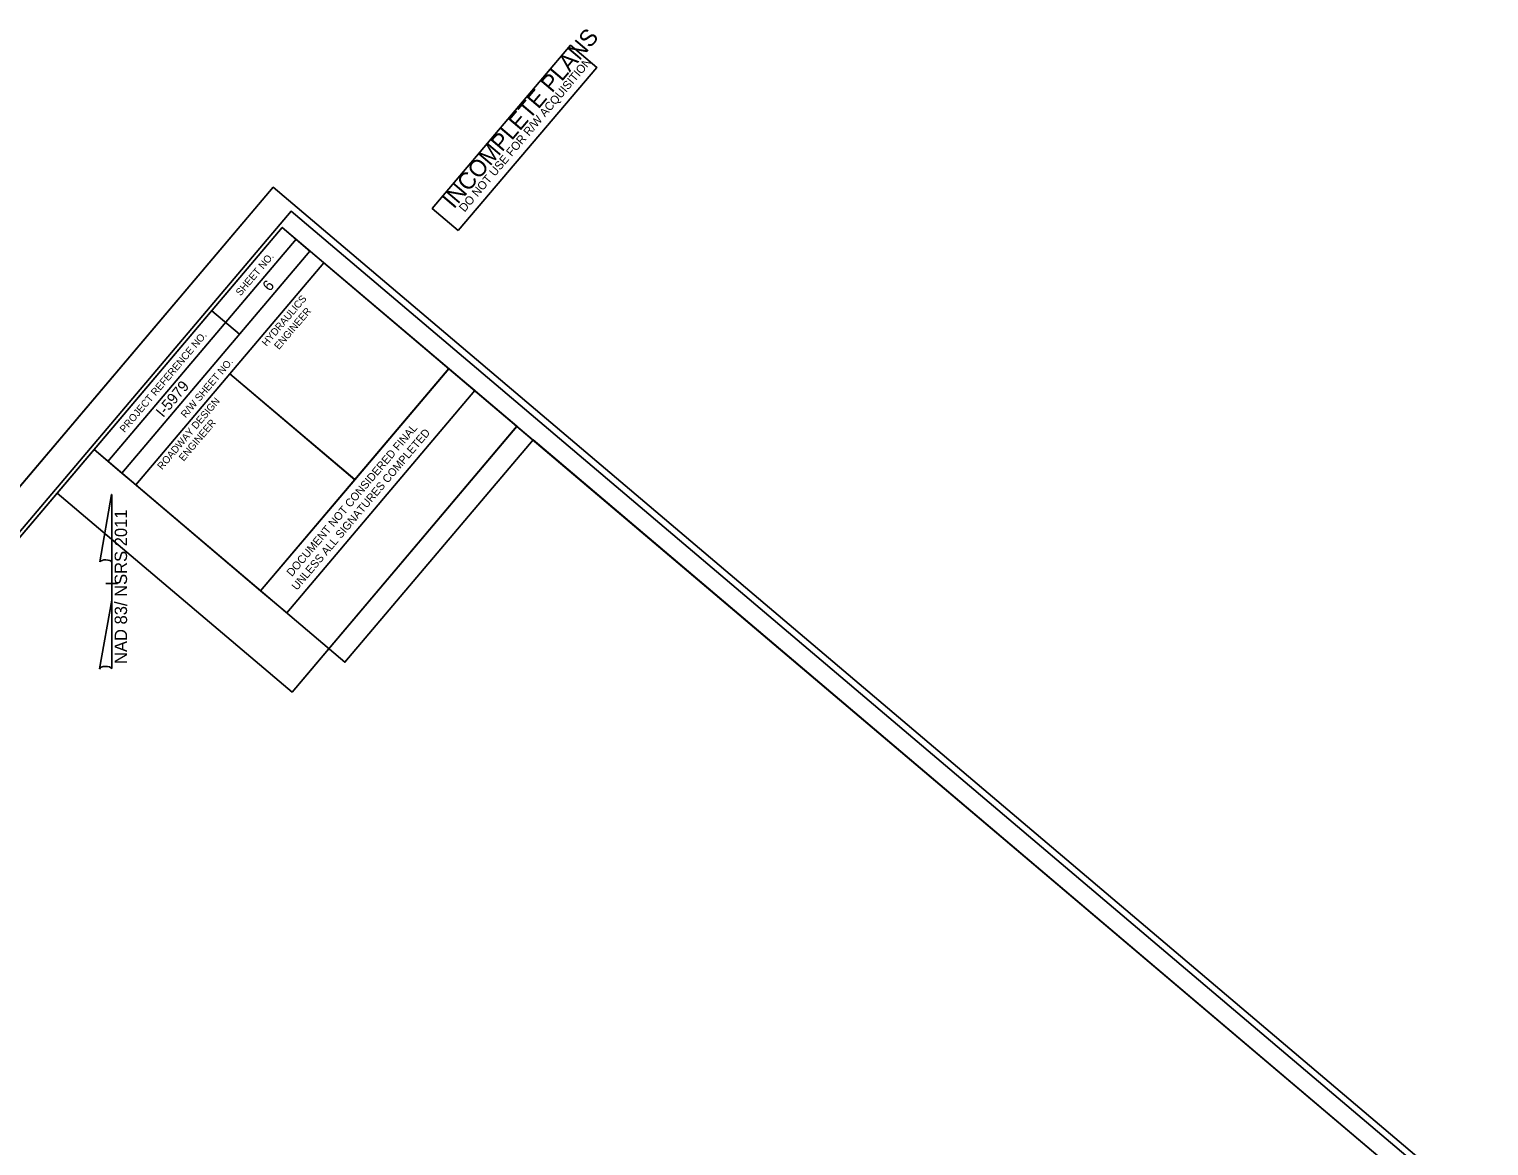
# Model space of a CAD drawing. Extents: x 1761124 to 1764673, y 421930 to 425955.
# Drawn here: x 1763670 to 1764673, y 425188 to 425955 of the extents above; entities that cross this region are included whole.
import ezdxf

# ---------------------------------------------------------------- set-up
doc = ezdxf.new("R2010")
doc.units = 0
for name, color, linetype in [('CTL Sheet Datum Description CELL', 7, 'Continuous'), ('Exist Roads Change in Surface', 7, 'Continuous'), ('Exist Roads Change in Surface Leader', 7, 'Continuous'), ('Exist Roads Change in Surface Text', 7, 'Continuous'), ('Exist Roads Curbs', 7, 'Continuous'), ('Exist Roads Curbs Leader', 7, 'Continuous'), ('Exist Roads EOP', 7, 'Continuous'), ('Exist Roads EOP Other', 7, 'Continuous'), ('Exist Roads EOP Text', 7, 'Continuous'), ('Exist Roads Soil', 7, 'Continuous'), ('Exist Structure Major Deck Tunnel Box Culvert', 7, 'Continuous')]:
    doc.layers.add(name, color=color, linetype=linetype)

msp = doc.modelspace()

# ---------------------------------------------------------------- linework, layer by layer
at = {"layer": 'CTL Sheet Datum Description CELL'}
msp.add_lwpolyline([(1763720.3, 424048.8), (1764644.8, 425140), (1764016.1, 425672.7), (1763886.8, 425520), (1763714.3, 425666.1), (1762919.2, 424727.5)], close=True, dxfattribs=at)
at = {"layer": 'Exist Roads Change in Surface'}
msp.add_lwpolyline([(1763584.8, 423853.9), (1764673, 425138.5), (1763837.5, 425846.3), (1762749.3, 424561.7)], close=True, dxfattribs=at)
at = {"layer": 'Exist Roads Change in Surface Leader'}
msp.add_lwpolyline([(1763964.7, 425816.6), (1763946.8, 425831.8), (1764041.8, 425943.9), (1764059.8, 425928.7)], close=True, dxfattribs=at)
at = {"layer": 'Exist Roads Change in Surface Text'}
msp.add_line((1763837.5, 425846.3), (1762749.3, 424561.7), dxfattribs=at)
at = {"layer": 'Exist Roads Curbs Leader'}
msp.add_line((1763726, 425567), (1763726, 425567), dxfattribs=at)
at = {"layer": 'Exist Roads EOP'}
for p, q in [((1763828.8, 425569.1), (1763958.1, 425721.8)), ((1763828.8, 425569.1), (1763958.1, 425721.8)), ((1763958.1, 425721.7), (1763976.1, 425706.6)), ((1763958.1, 425721.7), (1763976.1, 425706.6)), ((1763976.1, 425706.6), (1763846.8, 425553.9)), ((1763976.1, 425706.6), (1763846.8, 425553.9)), ((1763846.8, 425553.9), (1763828.8, 425569.1)), ((1763846.8, 425553.9), (1763828.8, 425569.1))]:
    msp.add_line(p, q, dxfattribs=at)
at = {"layer": 'Exist Roads EOP Other'}
for p, q in [((1763723.9, 425658), (1763853.2, 425810.6)), ((1763733.5, 425649.9), (1763862.7, 425802.5)), ((1763733.5, 425649.9), (1763862.7, 425802.5)), ((1763795.2, 425761.5), (1763814.3, 425745.3)), ((1763807.7, 425718.2), (1763893.5, 425645.5)), ((1763733.5, 425649.9), (1763743, 425641.8))]:
    msp.add_line(p, q, dxfattribs=at)
for points in [[(1763843.7, 425818.8), (1762874, 424674.2), (1763675.2, 423995.5), (1764644.8, 425140)], [(1763714.3, 425666.1), (1763843.7, 425818.8), (1763862.7, 425802.5), (1763733.5, 425649.9)], [(1763807.7, 425718.2), (1763872.3, 425794.5), (1763958.1, 425721.7), (1763893.5, 425645.4)], [(1763675.2, 423995.5), (1762874.1, 424674.2), (1763714.3, 425666.1), (1763828.8, 425569.1), (1763958.1, 425721.7), (1764644.8, 425140)], [(1763743, 425641.8), (1763807.7, 425718.2), (1763893.5, 425645.4), (1763828.8, 425569.1)]]:
    msp.add_lwpolyline(points, close=True, dxfattribs=at)
at = {"layer": 'Exist Roads EOP Text'}
for p, q in [((1763718.2, 425588.9), (1763726.4, 425635.2)), ((1763726.5, 425635.2), (1763726.4, 425635.2)), ((1763726.5, 425635.2), (1763726.4, 425635.2)), ((1763726.5, 425635.2), (1763726.5, 425587.4)), ((1763726.5, 425562.6), (1763726.5, 425588.8)), ((1763726.5, 425587.4), (1763726.5, 425588.8)), ((1763722.5, 425574.2), (1763722.4, 425574.2)), ((1763722.5, 425574.2), (1763730.5, 425574.2)), ((1763726, 425574.2), (1763722.5, 425574.2)), ((1763726.5, 425562.6), (1763718.1, 425515.4)), ((1763726.5, 425515.6), (1763726.5, 425562.6))]:
    msp.add_line(p, q, dxfattribs=at)
for centre, start_param, end_param in [((1763722.4, 425588.4), 0.216388, 2.908219), ((1763722.4, 425515.2), 0.201328, 3.141593)]:
    msp.add_ellipse(centre, major_axis=(4.23, -0.03), ratio=0.461098, start_param=start_param, end_param=end_param, dxfattribs=at)
at = {"layer": 'Exist Roads Soil'}
msp.add_lwpolyline([(1763577.9, 423876.8), (1764654.8, 425148), (1763849.8, 425829.9), (1762772.9, 424558.7)], close=True, dxfattribs=at)
at = {"layer": 'Exist Structure Major Deck Tunnel Box Culvert'}
for points in [[(1763850.4, 425499.5), (1764005, 425682.1), (1763843.7, 425818.8), (1763689, 425636.2)], [(1762874.1, 424674.2), (1763675.2, 423995.5), (1764644.8, 425140), (1764005, 425682), (1763850.4, 425499.5), (1763689, 425636.2)]]:
    msp.add_lwpolyline(points, close=True, dxfattribs=at)

# ---------------------------------------------------------------- texts
at = {"layer": 'Exist Roads Change in Surface Leader'}
for s, height, p in [('INCOMPLETE PLANS', 11.52, (1763961.6, 425831)), ('DO NOT USE FOR R/W ACQUISITION', 5.76, (1763969, 425828.9))]:
    msp.add_text(s, height=height, rotation=49.7301, dxfattribs=at).set_placement(p)
at = {"layer": 'Exist Roads Curbs'}
for s, p in [('6', (1763835.1, 425774.3)), ('I-5979', (1763761.8, 425687.7))]:
    msp.add_text(s, height=7.5, rotation=49.7301, dxfattribs=at).set_placement(p)
at = {"layer": 'Exist Roads EOP'}
for s, p in [('DOCUMENT NOT CONSIDERED FINAL', (1763850.3, 425578.5)), ('DOCUMENT NOT CONSIDERED FINAL', (1763850.3, 425578.5)), ('UNLESS ALL SIGNATURES COMPLETED', (1763853.8, 425569)), ('UNLESS ALL SIGNATURES COMPLETED', (1763853.8, 425569))]:
    msp.add_text(s, height=5.5, rotation=49.7301, dxfattribs=at).set_placement(p)
at = {"layer": 'Exist Roads EOP Other'}
for s, p in [('SHEET NO.', (1763815, 425771.3)), ('HYDRAULICS', (1763832.9, 425736.7)), ('ENGINEER', (1763841.4, 425734.4)), ('PROJECT REFERENCE NO.', (1763735.3, 425677.4)), ('R/W SHEET NO.', (1763777.3, 425687.5)), ('ROADWAY DESIGN', (1763761.1, 425651.9)), ('ENGINEER', (1763775.9, 425657.7))]:
    msp.add_text(s, height=5, rotation=49.7301, dxfattribs=at).set_placement(p)
at = {"layer": 'Exist Roads EOP Text'}
msp.add_text('NAD 83/ NSRS 2011', height=8.5, rotation=90, dxfattribs=at).set_placement((1763737, 425518.8))

doc.saveas('drawing.dxf')
